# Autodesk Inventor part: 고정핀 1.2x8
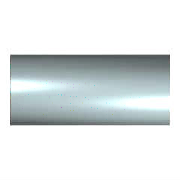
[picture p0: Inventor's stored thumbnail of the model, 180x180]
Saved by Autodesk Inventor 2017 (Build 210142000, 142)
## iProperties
IsCustomPart: 1
Created: 2012-02
Part Number: 고정핀 1.2x8
Material: 강철, 연강
Description: 평행 핀
Document SubType Name: Modeling
Standard: KS B 1320
Designer: P15F
Standards Organization: KS
Language: ko-KR
Size Designation: C 1.2 x  8
Categories: <MemberInstance><Categories><Category DisplayName="조임쇠" InternalName="e4da775c-781d-43d5-af7c-5136215cf5a6" Mnemonic="FSTN"><Category DisplayName="핀" InternalNa
Density: 1 g/cm^3
Appearance: 노란색
Author: P15F
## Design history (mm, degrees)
sketch "스케치1"
  geometry: C1 r 0.6 at (0, 0); 1 further point
  constraints: 1 centre point, 1 coincident
  dimensions: "d1" = 1.2 diameter of C1 (= NND)
extrude "본체" new body sketch "스케치1" distance "d2" = 8 (= NLG); taper "d3" = 0 deg
node "작업 평면1"
body "Solid1"
other parameters: "NND" = 1.2 [user parameter; used in 1 equation term], "NLG" = 8 [user parameter; used in 1 equation term], "d8" = 0, "d9" = 0, "d10" = 0
